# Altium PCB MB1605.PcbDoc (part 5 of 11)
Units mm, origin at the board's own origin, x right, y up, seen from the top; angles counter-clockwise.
Board outline 100 x 79.6 mm, 6 copper layers (Top Layer, Signal Layer 1, Signal Layer 2, Signal Layer 3, Signal Layer 4, Bottom Layer), stack 1.549 mm thick; 644 components, 529 nets, 2853 pads, 1462 vias.
Unrouted connection lines stored in the file: 2.
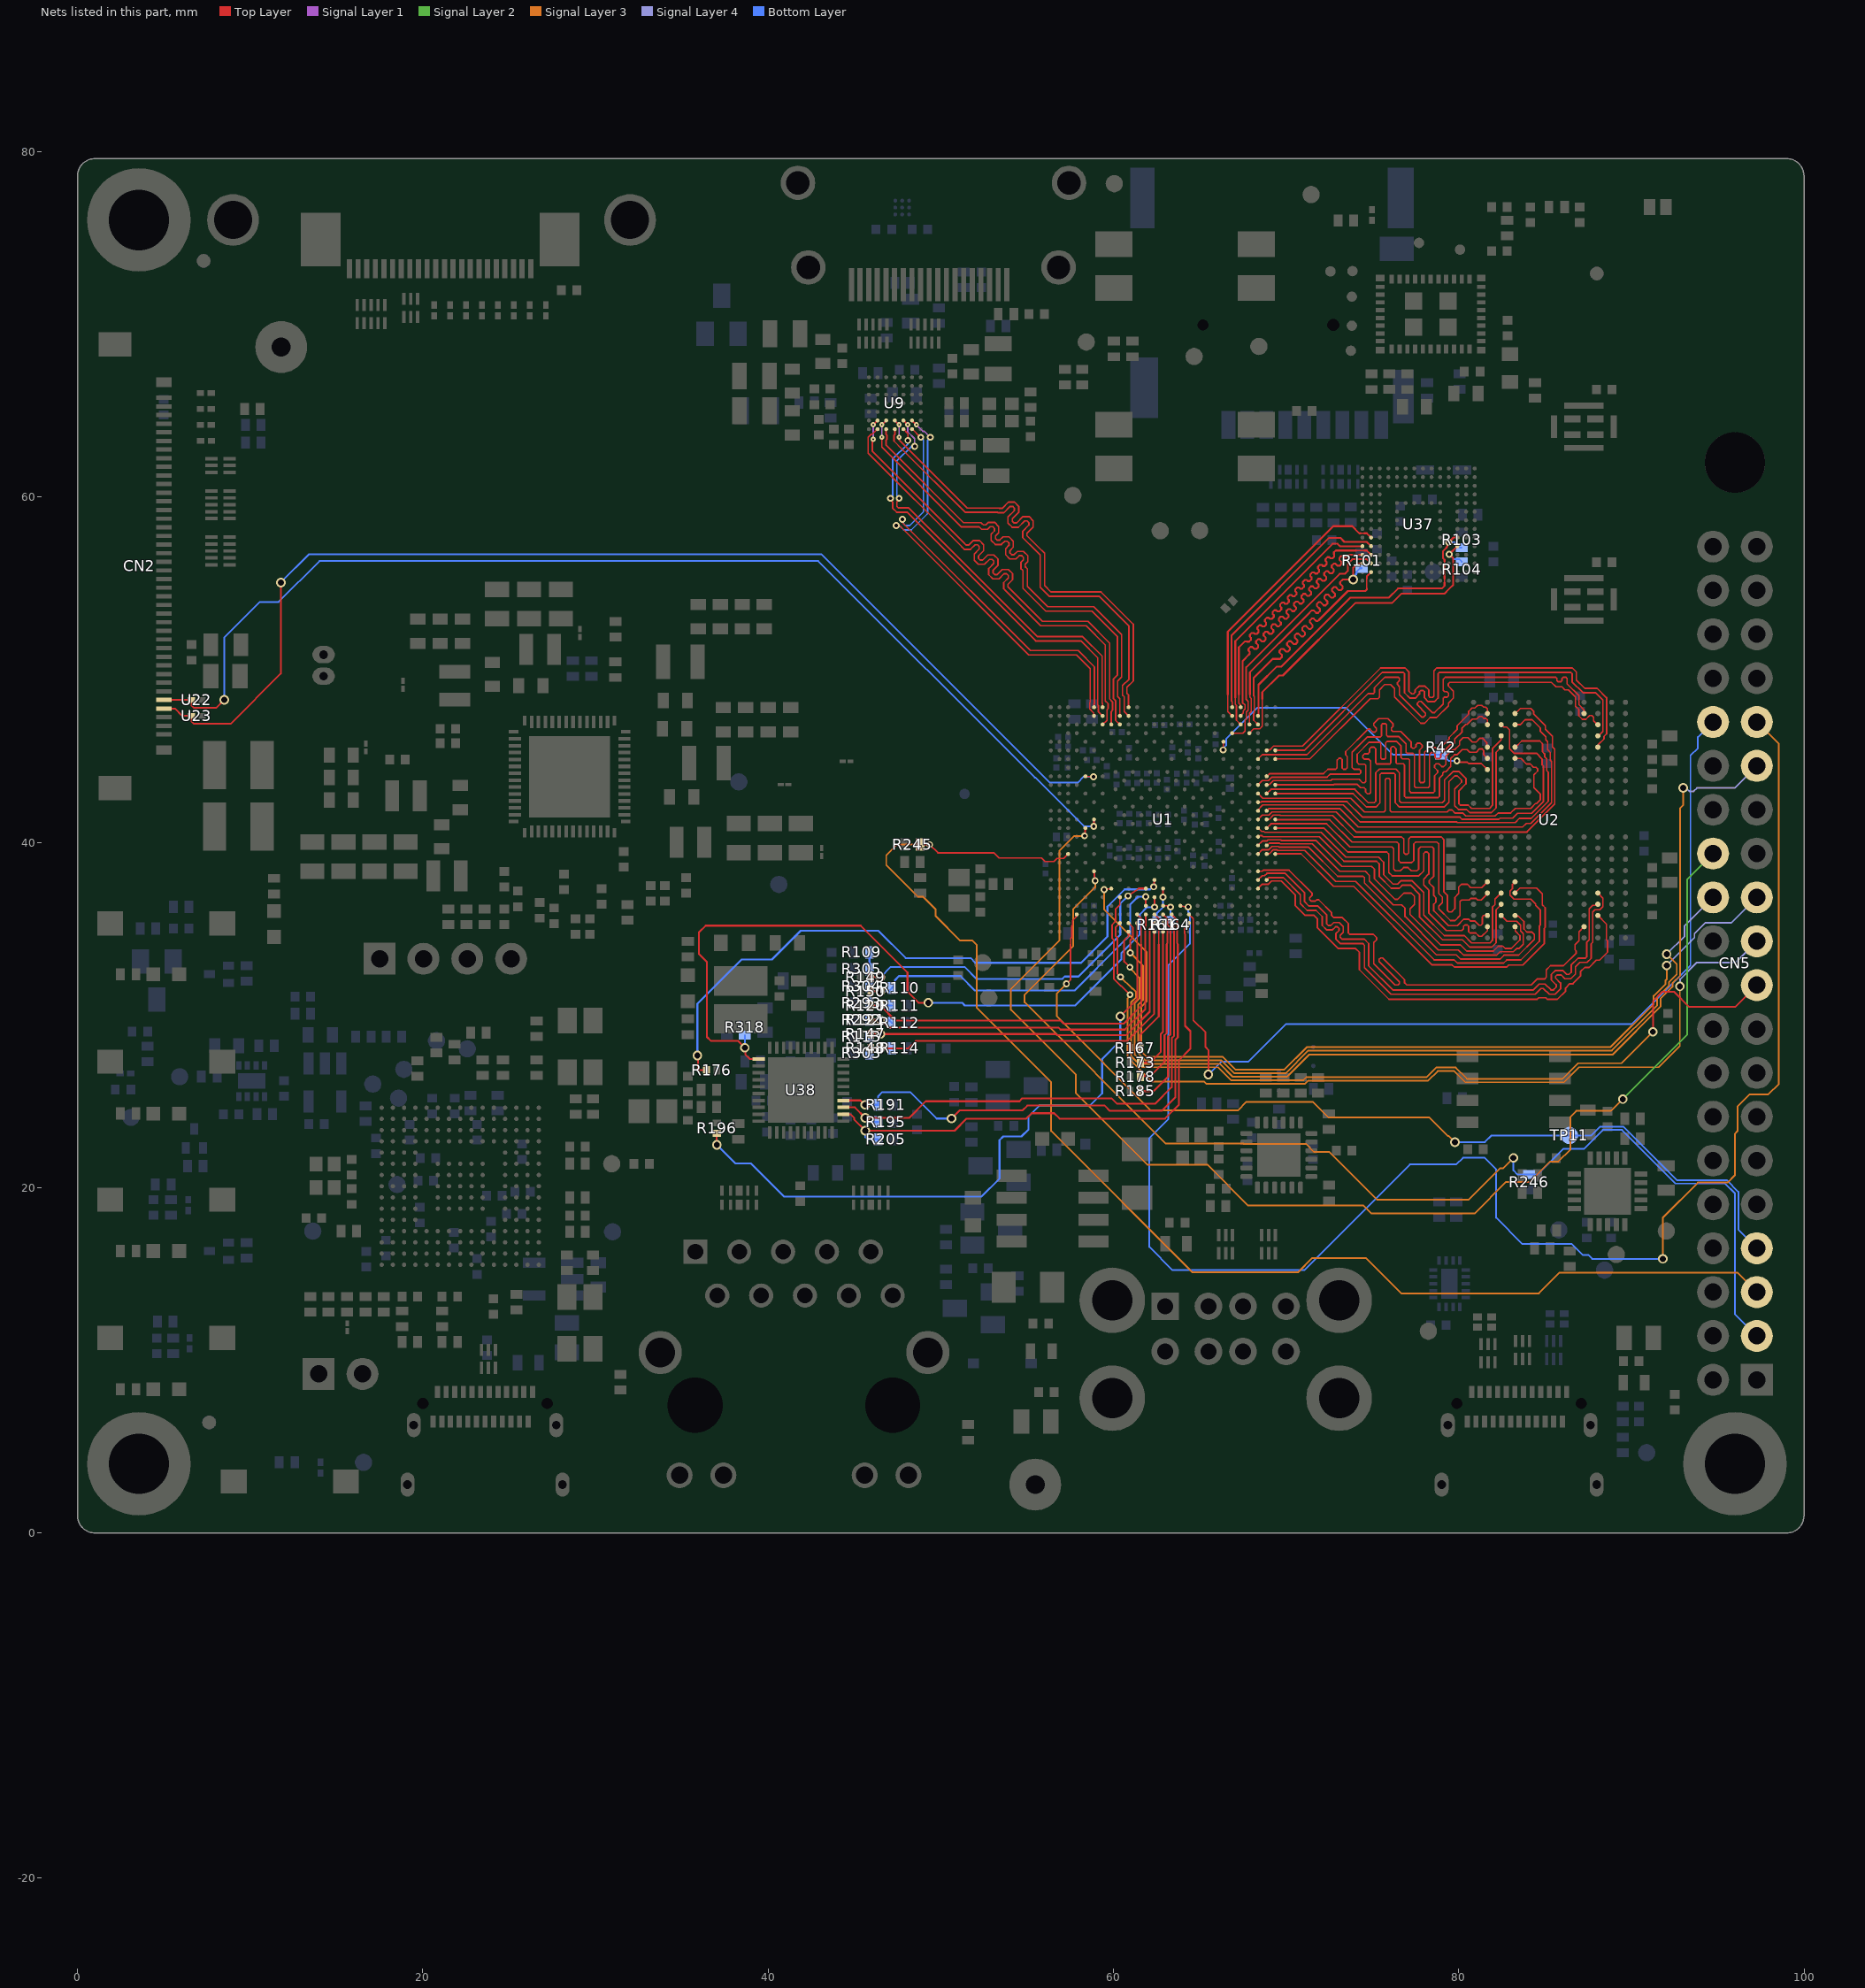
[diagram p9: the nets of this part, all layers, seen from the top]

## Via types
v1: diameter 0.55, hole 0.35, Top Layer to Bottom Layer, 823 vias
v2: diameter 0.4, hole 0.2, Top Layer to Bottom Layer, 235 vias
v3: diameter 0.4, hole 0.2, Top Layer to Bottom Layer, tented both sides, 216 vias
v4: diameter 0.5, hole 0.2, Top Layer to Bottom Layer, 159 vias
v5: diameter 0.25/0.3 (per signal layer), hole 0.1, Top Layer to Signal Layer 1, tented both sides, 29 vias

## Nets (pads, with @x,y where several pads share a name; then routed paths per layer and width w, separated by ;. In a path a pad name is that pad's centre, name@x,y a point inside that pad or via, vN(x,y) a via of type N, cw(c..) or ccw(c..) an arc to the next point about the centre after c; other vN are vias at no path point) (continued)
DDR_DQ7_A: U1.Y25 U2.B4 | length 29.9
  Top Layer w0.09: U1.Y25@68.375,38.325 68.62,38.325 68.682,38.387 70.174,38.387 71.498,37.064 71.498,36.927 71.365,36.794 71.365,36.68 71.444,36.601 71.698,36.601 71.771,36.674 71.888,36.674 72.636,35.926 72.636,35.768 72.76,35.644 73.257,35.644 73.606,35.296 73.606,34.757 73.682,34.681 75.04,34.681 75.246,34.476 75.246,34.362 75.076,34.192 75.076,32.969 76.305,31.74 76.487,31.74 76.565,31.818 76.565,31.925 75.391,33.098 75.391,33.218 75.481,33.307 75.593,33.307 76.865,32.035 76.865,31.863 76.988,31.74 84.199,31.74 84.54,32.082 84.963,32.082 85.073,32.191 85.073,32.614 85.316,32.858 86.072,32.858 86.807,33.593 86.807,33.701 86.731,33.777 86.731,34.064 86.964,34.297 86.964,34.819 U2.B4@87.26,35.115
DDR_DQ7_B: U1.G25 U2.AA4 | length 28.3
  Top Layer w0.09: U1.G25@68.377,44.829 68.623,45.075 71.214,45.075 74.754,48.614 75.062,48.614 75.12,48.672 75.12,48.958 75.722,49.56 76.504,49.56 76.569,49.494 76.569,49.369 76.455,49.254 76.455,49.134 76.569,49.02 76.569,48.547 77.854,47.262 77.97,47.262 78.08,47.372 78.08,47.483 77.609,47.954 77.609,48.064 77.706,48.161 77.814,48.161 78.456,47.518 78.6,47.518 79.099,48.016 79.099,48.341 79.169,48.412 79.329,48.412 79.403,48.485 79.403,48.642 79.316,48.729 79.17,48.729 79.099,48.8 79.099,49.443 79.216,49.56 85.622,49.56 ; 85.623,49.56 85.69,49.493 85.69,49.367 85.758,49.299 85.914,49.299 85.98,49.365 85.98,49.497 86.043,49.56 86.21,49.56 86.276,49.494 86.276,49.18 86.964,48.492 86.964,47.972 87.259,47.677 U2.AA4@87.259,47.444
DDR_DQ8_A: U1.R27 U2.B11 | length 20.4
  Top Layer w0.09: U1.R27@69.378,40.828 72.189,40.828 73.576,39.44 75.832,39.44 75.945,39.327 75.945,38.257 76.14,38.062 77.697,38.062 77.975,38.34 77.975,39.352 78.063,39.44 78.177,39.44 78.265,39.352 78.265,38.163 77.976,37.874 77.976,37.541 78.258,37.259 78.258,37.23 78.265,37.223 78.265,35.912 79.028,35.149 79.287,34.89 80.187,34.89 80.285,34.988 80.285,35.141 80.36,35.215 80.498,35.215 80.575,35.138 80.575,34.826 80.65,34.751 80.987,34.751 81.183,34.555 81.332,34.555 81.659,34.882 U2.B11@81.66,35.115
DDR_DQ8_B: U1.J26 U2.AA11 | length 23.9
  Top Layer w0.09: U1.J26@68.877,43.829 68.915,43.829 69.065,43.979 72.169,43.979 72.425,44.235 72.874,44.235 72.954,44.314 72.954,44.764 73.065,44.875 73.172,44.875 73.243,44.804 73.243,44.315 73.324,44.235 73.454,44.235 73.536,44.316 73.536,44.977 73.449,45.063 73.449,45.259 74.749,46.559 74.863,46.559 75.035,46.387 75.157,46.387 75.235,46.465 75.235,46.605 75.074,46.767 75.074,46.884 75.354,47.164 75.901,47.164 76.198,46.867 76.198,46.72 76.106,46.628 76.106,46.499 76.182,46.423 76.642,46.423 77.239,45.827 77.239,45.535 77.328,45.446 77.425,45.446 77.529,45.55 77.529,45.662 77.605,45.738 77.77,45.738 77.886,45.622 77.886,45.497 77.73,45.342 77.73,43.53 77.8,43.46 77.952,43.46 78.02,43.528 78.02,45.22 78.29,45.49 78.658,45.49 78.748,45.399 78.851,45.399 79.448,45.997 79.448,46.076 79.903,46.531 ; 79.904,46.531 79.904,46.746 80.575,47.417 80.575,47.583 80.771,47.779 80.931,47.779 81.091,47.939 81.34,47.939 81.449,47.83 81.563,47.83 81.659,47.734 U2.AA11@81.66,47.465
DDR_DQ9_A: U1.R26 U2.C11 | length 21.2
  Top Layer w0.09: U1.R26@68.875,40.825 69.125,41.075 72.352,41.075 73.697,39.73 76.134,39.73 76.235,39.629 76.235,38.453 76.336,38.352 76.622,38.352 76.809,38.539 77.063,38.539 77.25,38.352 77.577,38.352 77.685,38.46 77.685,39.625 77.79,39.73 78.453,39.73 78.555,39.628 78.555,38.043 78.292,37.78 78.292,37.635 78.555,37.372 78.555,36.912 78.676,36.791 78.676,36.538 78.555,36.417 78.555,36.032 79.407,35.18 79.914,35.18 ; 79.915,35.18 80.279,35.545 80.578,35.545 80.674,35.449 80.929,35.449 81.182,35.196 81.29,35.196 81.367,35.274 81.367,35.691 81.436,35.759 81.654,35.759 U2.C11@81.66,35.765
DDR_DQ9_B: U1.K25 U2.Y11 | length 23.9
  Top Layer w0.09: U1.K25@68.375,43.325 68.625,43.575 68.984,43.575 69.183,43.774 72.374,43.774 72.545,43.945 74.245,43.945 74.323,44.023 74.323,44.15 74.236,44.237 73.921,44.237 73.826,44.333 73.826,45.226 74.697,46.097 75.451,46.097 75.525,46.172 75.525,46.802 75.598,46.874 75.74,46.874 75.816,46.799 75.816,46.203 75.886,46.133 76.522,46.133 76.949,45.706 76.949,45.225 77.018,45.156 77.361,45.156 77.44,45.077 77.44,43.24 77.51,43.17 78.237,43.17 78.31,43.243 78.31,45.1 78.41,45.2 78.537,45.2 78.629,45.108 78.629,44.919 78.706,44.842 78.874,44.842 78.954,44.923 78.954,45.093 79.515,45.654 79.655,45.654 ; 79.656,45.654 79.765,45.763 79.765,45.982 79.769,45.982 80.194,46.407 80.194,46.626 80.403,46.835 80.477,46.835 80.783,47.142 81.038,47.142 81.196,47.3 81.327,47.3 81.447,47.18 81.577,47.18 81.659,47.097 U2.Y11@81.66,46.815
DDR_DQ10_A: U1.P27 U2.E11 | length 20.4
  Top Layer w0.09: U1.P27@69.377,41.329 69.401,41.305 72.532,41.305 73.817,40.02 76.417,40.02 76.525,39.912 76.525,38.936 76.632,38.829 77.276,38.829 77.395,38.948 77.395,39.902 77.513,40.02 78.731,40.02 78.845,39.906 78.845,37.032 79.049,36.828 79.049,36.501 78.845,36.297 78.845,36.152 79.527,35.47 79.795,35.47 80.08,35.755 80.08,36.576 80.171,36.667 80.608,36.667 80.69,36.749 81.006,36.749 81.1,36.655 81.304,36.655 81.66,37.01 U2.E11@81.66,37.065
DDR_DQ10_B: U1.K26 U2.V11 | length 23.8
  Top Layer w0.09: U1.K26@68.877,43.329 68.898,43.35 69.03,43.35 69.257,43.578 72.588,43.578 72.665,43.655 74.226,43.655 74.426,43.456 74.544,43.456 74.613,43.525 74.613,44.465 74.55,44.527 74.217,44.527 74.116,44.629 74.116,45.105 74.809,45.799 75.413,45.799 75.484,45.728 75.484,44.878 75.536,44.825 75.722,44.825 75.775,44.878 75.775,45.768 75.85,45.843 76.402,45.843 76.659,45.586 76.659,44.906 76.729,44.836 77.082,44.836 77.15,44.768 77.15,42.954 77.224,42.88 78.527,42.88 78.6,42.953 78.6,43.859 78.782,44.041 78.782,44.151 78.6,44.333 78.6,44.461 78.691,44.552 78.848,44.552 79.015,44.385 79.126,44.385 79.253,44.512 79.253,44.982 79.635,45.364 79.776,45.364 80.055,45.643 80.055,45.862 80.257,46.064 80.543,46.064 80.798,45.809 81.011,45.809 81.231,46.029 81.379,46.029 81.62,45.788 81.62,45.554 U2.V11@81.66,45.515
DDR_DQ11_A: U1.P26 U2.F11 | length 20.8
  Top Layer w0.09: U1.P26@68.877,41.329 68.887,41.339 69.035,41.339 69.271,41.575 69.638,41.575 69.658,41.555 72.692,41.555 73.937,40.31 76.699,40.31 76.815,40.194 76.815,39.398 76.897,39.316 77.031,39.316 77.105,39.39 77.105,40.203 77.212,40.31 79.002,40.31 79.135,40.177 79.135,37.152 79.342,36.945 79.342,36.066 79.439,35.968 79.583,35.968 79.779,36.165 79.779,36.816 80.002,37.04 80.002,37.417 80.155,37.569 80.502,37.569 80.697,37.374 81.331,37.374 U2.F11@81.666,37.709
DDR_DQ11_B: U1.K27 U2.U11 | length 23.1
  Top Layer w0.09: U1.K27@69.377,43.329 69.388,43.34 72.76,43.34 72.785,43.365 74.106,43.365 74.305,43.166 74.514,43.166 74.604,43.076 74.604,42.916 74.709,42.81 74.817,42.81 74.903,42.896 74.903,44.715 74.801,44.817 74.539,44.817 74.441,44.915 74.441,45.021 74.554,45.134 74.755,45.134 74.835,45.214 74.835,45.415 74.929,45.509 75.106,45.509 75.194,45.421 75.194,44.6 75.259,44.535 75.994,44.535 76.065,44.606 76.065,45.473 76.145,45.553 76.244,45.553 76.369,45.428 76.369,44.616 76.438,44.546 76.788,44.546 76.86,44.474 76.86,42.666 76.937,42.59 78.805,42.59 78.89,42.675 78.89,43.739 79.072,43.921 79.072,44.007 79.16,44.095 79.246,44.095 79.543,44.392 79.543,44.861 79.756,45.074 ; 79.757,45.074 79.896,45.074 80.196,45.374 80.482,45.374 80.636,45.22 81.018,45.22 81.212,45.414 81.35,45.414 81.44,45.324 81.44,45.085 U2.U11@81.66,44.865
DDR_DQ12_A: U1.V26 U2.F9 | length 24
  Top Layer w0.09: U1.V26@68.875,39.325 68.889,39.339 69.035,39.339 69.271,39.575 69.479,39.575 69.525,39.529 71.083,39.529 72.872,37.74 74.033,37.74 78.583,33.19 78.607,33.19 79.737,33.19 79.918,33.01 82.602,33.01 82.782,33.19 83.598,33.19 84.671,34.263 84.671,35.154 84.72,35.203 84.72,36.094 84.451,36.363 84.451,36.43 84.168,36.713 83.209,36.713 82.975,36.947 82.975,37.183 83.112,37.32 83.112,37.567 U2.F9@83.26,37.715
DDR_DQ12_B: U1.L25 U2.U9 | length 24.7
  Top Layer w0.09: U1.L25@68.377,42.829 68.647,42.559 73.739,42.559 74.537,41.76 75.661,41.76 75.74,41.839 75.74,43.628 75.817,43.705 75.956,43.705 76.03,43.631 76.03,41.834 76.105,41.76 79.329,41.76 79.441,41.872 79.607,41.872 79.791,41.689 ; 79.792,41.689 80.248,41.689 80.408,41.529 82.109,41.529 82.275,41.695 83.003,41.695 83.277,41.969 84.169,41.969 84.445,42.244 84.517,42.244 84.719,42.446 84.719,42.814 84.355,43.178 84.355,43.916 84.569,44.13 84.569,44.254 84.476,44.347 84.354,44.347 84.352,44.349 84.336,44.349 84.145,44.54 83.927,44.54 83.602,44.865 U2.U9@83.26,44.865
DDR_DQ13_A: U1.V27 U2.E9 | length 23.7
  Top Layer w0.09: U1.V27@69.377,39.329 69.387,39.339 70.863,39.339 72.752,37.45 73.913,37.45 78.462,32.9 78.465,32.9 79.616,32.9 79.737,32.78 ; 79.738,32.78 82.782,32.78 82.902,32.9 83.718,32.9 84.961,34.143 84.961,35.027 85.01,35.075 85.01,36.214 84.839,36.385 84.839,37.024 84.513,37.35 83.545,37.35 U2.E9@83.26,37.065
DDR_DQ13_B: U1.N25 U2.V9 | length 23.2
  Top Layer w0.09: U1.N25@68.377,41.829 68.377,41.891 68.653,42.167 73.311,42.167 74.297,41.18 79.884,41.18 ; 79.886,41.18 79.921,41.144 83.272,41.144 83.517,41.389 84.204,41.389 85.184,42.369 85.184,44.071 85.1,44.155 85.1,44.832 84.977,44.955 84.977,45.126 84.854,45.249 84.854,45.713 84.698,45.869 83.648,45.869 83.273,45.494 U2.V9@83.259,45.494
DDR_DQ14_A: U1.V25 U2.C9 | length 21.7
  Top Layer w0.09: U1.V25@68.377,39.329 68.623,39.575 69.003,39.575 69.193,39.765 69.557,39.765 69.603,39.719 71.303,39.719 72.992,38.03 74.466,38.03 74.535,37.961 74.535,37.648 78.703,33.48 79.858,33.48 80.098,33.24 82.4,33.24 82.63,33.47 83.468,33.47 84.381,34.383 84.381,34.666 84.25,34.797 83.958,34.797 83.775,34.98 83.775,35.413 83.463,35.725 83.3,35.725 U2.C9@83.26,35.765
DDR_DQ14_B: U1.N26 U2.Y9 | length 24
  Top Layer w0.09: U1.N26@68.875,41.825 69.008,41.958 73.109,41.958 74.177,40.89 83.701,40.89 83.91,41.099 84.183,41.099 85.374,42.29 85.374,44.689 85.307,44.756 85.307,45.206 85.144,45.369 85.144,45.833 85.044,45.933 85.044,46.117 84.729,46.432 84.729,46.632 84.725,46.632 84.257,47.1 83.84,47.1 83.554,46.814 U2.Y9@83.26,46.815
DDR_DQ15_A: U1.U25 U2.B9 | length 20.8
  Top Layer w0.09: U1.U25@68.377,39.829 68.625,40.077 68.894,40.077 68.956,40.14 69.692,40.14 69.727,40.104 71.739,40.104 73.233,38.61 74.955,38.61 75.115,38.45 75.115,37.888 76.306,36.697 76.458,36.697 76.816,37.055 77.259,37.055 77.435,36.879 77.435,36.413 77.178,36.156 77.178,35.825 78.943,34.06 80.098,34.06 80.458,33.7 82.011,33.7 82.293,33.982 82.56,33.982 82.687,33.855 83.053,33.855 83.545,34.347 83.545,34.593 83.28,34.858 83.28,35.073 U2.B9@83.259,35.094
DDR_DQ15_B: U1.P25 U2.AA9 | length 25.7
  Top Layer w0.09: U1.P25@68.377,41.329 68.623,41.575 69.003,41.575 69.193,41.765 72.892,41.765 74.057,40.6 83.953,40.6 85.564,42.211 85.564,45.392 85.434,45.522 85.434,46.138 85.019,46.553 85.019,46.752 84.345,47.426 84.345,47.583 84.178,47.75 83.572,47.75 U2.AA9@83.266,47.444
DDR_DQMI0_A: U1.AB25 U2.C3 | length 28.3
  Top Layer w0.09: U1.AB25@68.375,37.325 68.375,37.336 68.614,37.575 68.979,37.575 69.169,37.765 69.722,37.765 70.535,36.952 70.535,36.336 71.1,35.771 71.617,35.771 71.806,35.582 71.806,35.066 72.238,34.633 73.02,33.851 74.022,33.851 74.246,33.627 74.246,32.625 75.961,30.91 84.543,30.91 84.628,30.995 85.037,30.995 85.122,30.91 85.714,30.91 86.19,31.386 86.19,31.567 86.434,31.811 86.615,31.811 87.053,32.249 87.053,32.512 87.295,32.754 87.558,32.754 87.975,33.171 88.159,33.171 88.619,33.632 88.619,34.303 88.559,34.363 88.559,35.266 U2.C3@88.06,35.765
DDR_DQMI0_B: U1.G27 U2.Y3 | length 25.8
  Top Layer w0.09: U1.G27@69.377,44.829 71.378,44.829 74.874,48.324 75.323,48.324 75.41,48.412 75.41,48.838 75.708,49.136 76.043,49.136 76.279,48.9 76.279,48.426 77.807,46.898 78.017,46.898 78.346,47.228 78.721,47.228 79.403,47.911 79.403,48.068 79.693,48.358 ; 79.694,48.358 79.694,48.761 79.398,49.057 79.398,49.19 79.478,49.27 85.368,49.27 ; 85.369,49.27 85.63,49.009 85.981,49.009 86.156,48.834 86.353,48.834 86.764,48.423 86.764,47.889 86.952,47.701 86.952,47.333 87.16,47.126 87.365,47.126 87.587,47.347 87.719,47.347 87.815,47.251 87.815,47.033 88.034,46.815 U2.Y3@88.06,46.815
DDR_DQMI1_A: U1.U26 U2.C10 | length 20.8
  Top Layer w0.09: U1.U26@68.875,39.825 68.91,39.825 69.038,39.953 69.624,39.953 69.663,39.914 71.519,39.914 73.113,38.32 74.586,38.32 74.825,38.081 74.825,37.768 76.209,36.384 76.689,36.384 76.888,36.185 76.888,35.705 78.823,33.77 79.978,33.77 80.278,33.47 82.204,33.47 82.394,33.66 83.161,33.66 83.351,33.85 83.492,33.85 83.735,34.093 83.735,34.722 83.584,34.873 83.584,35.194 83.347,35.431 82.794,35.431 U2.C10@82.46,35.765
DDR_DQMI1_B: U1.M25 U2.Y10 | length 23.7
  Top Layer w0.09: U1.M25@68.375,42.325 68.378,42.328 68.545,42.328 68.574,42.357 73.531,42.357 74.417,41.47 80.05,41.47 80.181,41.339 82.329,41.339 82.395,41.405 83.123,41.405 83.397,41.679 84.221,41.679 84.909,42.367 84.909,44.413 84.824,44.498 84.824,44.839 84.505,45.159 83.208,45.159 82.944,45.423 82.944,46.513 82.781,46.677 82.618,46.677 82.479,46.815 U2.Y10@82.459,46.815
DDR_DQS0_A_N: U1.AA26 U2.E3 | length 30.5
  Top Layer w0.09: U1.AA26@68.875,37.825 68.875,37.832 68.998,37.955 69.843,37.955 70.825,36.973 70.825,36.456 71.22,36.061 71.737,36.061 72.096,35.702 72.096,35.186 72.346,34.935 72.695,34.935 72.863,35.104 72.982,35.104 73.066,35.02 73.066,34.896 72.882,34.712 72.882,34.399 73.14,34.141 74.43,34.141 74.536,34.036 74.536,32.746 76.081,31.2 84.422,31.2 84.764,31.542 84.9,31.542 85.242,31.2 85.594,31.2 85.9,31.506 85.9,31.852 85.613,32.139 85.613,32.242 85.688,32.318 85.933,32.318 86.149,32.101 86.495,32.101 86.763,32.369 86.763,32.785 87.022,33.044 87.438,33.044 87.671,33.277 87.671,34.119 87.764,34.212 87.764,35.978 87.885,36.099 88.181,36.099 88.354,36.272 88.354,36.771 U2.E3@88.06,37.065
DDR_DQS0_A_P: U1.AA25 U2.D3 | length 29.9
  Top Layer w0.09: U1.AA25@68.375,37.825 68.62,38.07 68.76,38.07 68.894,38.205 69.947,38.205 71.075,37.077 71.075,36.56 71.324,36.311 71.841,36.311 72.346,35.806 72.346,35.289 72.449,35.185 72.591,35.185 72.76,35.354 73.086,35.354 73.316,35.124 73.316,34.792 73.132,34.608 73.132,34.503 73.243,34.391 74.534,34.391 74.786,34.139 74.786,32.849 76.185,31.45 84.319,31.45 84.66,31.792 85.004,31.792 85.345,31.45 85.49,31.45 85.65,31.609 85.65,31.748 85.363,32.035 85.363,32.346 85.584,32.568 86.037,32.568 86.253,32.351 86.392,32.351 86.513,32.473 86.513,32.888 86.919,33.294 87.334,33.294 87.421,33.381 87.421,34.223 87.554,34.356 87.554,36.145 87.758,36.349 87.937,36.349 88.003,36.415 U2.D3@88.06,36.415
DDR_DQS0_B_N: U1.F26 U2.V3 | length 29.3
  Top Layer w0.09: U1.F26@68.877,45.329 68.904,45.356 69.05,45.356 69.273,45.579 70.955,45.579 75.475,50.1 76.893,50.1 77.109,49.883 77.109,48.77 77.278,48.602 77.383,48.602 77.477,48.696 77.477,48.829 77.692,49.044 78.052,49.044 78.269,48.827 78.269,48.469 78.34,48.398 78.492,48.398 78.559,48.465 78.559,49.937 78.722,50.1 86.587,50.1 86.816,49.872 86.816,49.404 87.299,48.92 88.022,48.92 88.564,48.378 88.564,46.284 88.414,46.134 88.414,45.997 88.093,45.676 88.093,45.528 U2.V3@88.059,45.494
DDR_DQS0_B_P: U1.F27 U2.W3 | length 27.5
  Top Layer w0.09: U1.F27@69.377,45.329 71.058,45.329 75.579,49.85 76.789,49.85 ; 76.795,49.843 76.859,49.78 76.859,48.667 77.174,48.352 77.487,48.352 77.727,48.592 77.727,48.726 77.795,48.794 77.949,48.794 78.019,48.724 78.019,48.366 78.236,48.148 78.595,48.148 78.809,48.362 78.809,49.777 78.882,49.85 86.484,49.85 86.566,49.768 86.566,49.3 87.196,48.67 87.918,48.67 88.354,48.234 88.354,46.427 88.071,46.144 U2.W3@88.059,46.144
DDR_DQS1_A_N: U1.R25 U2.E10 | length 20.7
  Top Layer w0.09: U1.R25@68.375,40.825 68.392,40.825 68.584,40.633 68.713,40.633 68.771,40.575 72.031,40.575 73.456,39.15 75.351,39.15 75.655,38.846 75.655,38.127 76.195,37.587 76.454,37.587 76.638,37.772 77.306,37.772 77.975,37.103 77.975,35.792 79.167,34.6 80.32,34.6 ; 80.321,34.6 80.742,34.18 81.812,34.18 81.954,34.322 81.954,36.243 82.104,36.393 82.104,36.709 U2.E10@82.46,37.065
DDR_DQS1_A_P: U1.T25 U2.D10 | length 20.3
  Top Layer w0.09: U1.T25@68.375,40.325 68.413,40.325 68.471,40.383 68.61,40.383 68.668,40.325 71.928,40.325 73.353,38.9 75.247,38.9 75.405,38.742 75.405,38.024 76.091,37.337 76.557,37.337 76.742,37.522 77.202,37.522 77.725,36.999 77.725,35.689 79.063,34.35 80.217,34.35 ; 80.218,34.351 80.638,33.93 81.916,33.93 82.164,34.178 82.164,36.099 U2.D10@82.459,36.394
DDR_DQS1_B_N: U1.L27 U2.V10 | length 24.1
  Top Layer w0.09: U1.L27@69.377,42.825 73.816,42.825 ; 73.827,42.825 73.883,42.825 74.658,42.05 75.208,42.05 75.443,42.285 75.443,43.927 75.511,43.995 76.251,43.995 76.32,43.926 76.32,42.298 76.569,42.05 79.156,42.05 79.43,42.324 79.43,43.515 79.765,43.85 ; 79.766,43.85 79.912,43.85 80.167,43.596 80.167,43.491 79.764,43.088 79.764,42.127 79.984,41.907 80.447,41.907 80.633,41.72 81.89,41.72 82.164,41.994 82.164,45.219 U2.V10@82.46,45.515
DDR_DQS1_B_P: U1.L26 U2.W10 | length 25.1
  Top Layer w0.09: U1.L26@68.877,42.829 68.879,42.829 69.125,43.075 73.986,43.075 74.761,42.3 75.105,42.3 75.193,42.388 75.193,44.031 75.407,44.245 76.355,44.245 76.57,44.03 76.57,42.402 76.672,42.3 79.052,42.3 79.18,42.427 79.18,43.618 79.662,44.1 ; 79.663,44.1 80.016,44.1 80.417,43.699 80.417,43.387 80.014,42.984 80.014,42.23 80.088,42.157 80.55,42.157 80.737,41.97 81.786,41.97 81.954,42.138 81.954,45.427 82.464,45.937 82.464,46.161 U2.W10@82.46,46.165
DDR_RESETN: R42.2 U1.E21 U2.T11 | length 18.6
  Top Layer w0.09: v3(66.35,45.35) 66.362,45.363 66.362,45.812 U1.E21@66.375,45.825 ; v2@79.881,44.707 79.994,44.707 80.065,44.636 80.492,44.636 80.562,44.565 81.31,44.565 U2.T11@81.66,44.215
  Bottom Layer w0.09: v3(66.35,45.35) 66.35,45.434 66.53,45.614 66.53,45.984 68.346,47.8 73.473,47.8 76.198,45.074 79.065,45.074 79.414,44.724 v2(79.895,44.725)
DISP.BLCTRL: CN2.37 U1.J5 U23.1 | length 67.7
  Top Layer w0.09: U1.J5@58.375,43.825 58.388,43.813 58.862,43.813 v3@58.875,43.8
  Top Layer w0.1: CN2.37@5,47.75 5.639,47.75 6.064,47.325 U23.1@6.596,47.325 6.596,47.009 6.738,46.867 8.873,46.867 11.775,49.769 v1(11.775,55.05)
  Bottom Layer w0.1: v1(11.775,55.05) 13.418,56.693 43.07,56.693 55.621,44.142 55.625,44.142 55.635,44.142 56.314,43.463 57.927,43.463 58.264,43.8 v3(58.85,43.8)
DISP.LED_EN: CN2.36 U1.P6 U22.1 | length 66.6
  Top Layer w0.09: v3(58.858,40.933) 58.877,40.952 58.877,41.323 U1.P6@58.875,41.325
  Top Layer w0.1: CN2.36@5,48.25 U22.1@6.596,48.25 6.596,47.934 6.738,47.792 8.033,47.792 v1(8.496,48.255)
  Bottom Layer w0.1: v1(8.496,48.255) 8.496,51.846 10.57,53.92 11.645,53.92 14.018,56.293 42.904,56.293 55.445,43.752 55.468,43.752 58.287,40.933 v3(58.858,40.933)
DSI_CLK_N: U1.C8 U9.F2 | length 28.3
  Top Layer w0.09: v5(46.086,63.342) 46.041,63.297 46.041,62.648 51.386,57.303 51.47,57.219 51.616,57.219 51.882,57.485 52.235,57.485 52.479,57.241 52.479,56.888 52.186,56.596 52.186,56.45 52.284,56.353 52.43,56.353 52.722,56.645 53.075,56.645 53.319,56.401 53.319,56.048 53.026,55.756 53.026,55.61 53.124,55.513 53.27,55.513 53.562,55.805 53.915,55.805 54.159,55.561 54.159,55.208 53.893,54.942 53.893,54.796 53.939,54.75 54.023,54.666 55.891,52.798 58.519,52.798 59.781,51.536 59.781,48.304 59.945,48.14 59.945,47.649 59.875,47.579 59.875,47.07 U1.C8@59.875,46.825 ; v5(46.086,64.185) U9.F2@46.336,64.435
  Signal Layer 1 w0.09: v5(46.086,63.342) v5(46.086,64.185)
DSI_CLK_P: U1.C7 U9.G2 | length 28.1
  Top Layer w0.09: U9.G2@46.336,63.935 46.038,63.637 45.964,63.637 45.791,63.464 45.791,62.544 51.21,57.126 51.293,57.042 51.367,56.969 51.72,56.969 51.986,57.235 52.132,57.235 52.229,57.138 52.229,56.992 51.936,56.699 51.936,56.346 52.18,56.103 52.533,56.103 52.826,56.395 52.972,56.395 53.069,56.298 53.069,56.152 52.776,55.859 52.776,55.506 53.02,55.263 53.373,55.263 53.666,55.555 53.812,55.555 53.909,55.458 53.909,55.312 53.643,55.046 53.643,54.693 53.762,54.573 53.846,54.489 55.788,52.548 58.415,52.548 59.531,51.432 59.531,48.2 59.695,48.036 59.695,47.752 59.625,47.682 59.625,47.174 59.625,47.073 59.377,46.825 U1.C7@59.375,46.825
DSI_D0_N: U1.C9 U9.F3 | length 28.2
  Top Layer w0.09: v5(46.586,63.464) 46.586,62.892 51.208,58.27 52.183,58.27 52.229,58.27 52.29,58.209 52.363,58.136 52.716,58.136 52.864,58.284 53.01,58.284 53.107,58.186 53.107,58.04 52.917,57.851 52.917,57.498 53.161,57.254 53.514,57.254 53.704,57.444 53.85,57.444 53.947,57.346 53.947,57.2 53.757,57.011 53.757,56.658 54.001,56.414 54.354,56.414 54.544,56.604 54.69,56.604 54.787,56.506 54.787,56.36 54.639,56.213 54.639,55.86 54.729,55.77 54.764,55.735 54.764,55.638 54.764,54.715 56.082,53.397 58.764,53.397 60.225,51.936 60.225,49.675 59.995,49.445 59.995,48.575 59.995,48.344 60.068,48.271 60.125,48.214 60.125,47.429 60.125,47.075 U1.C9@60.375,46.825 ; v5(46.586,64.185) U9.F3@46.836,64.435
  Signal Layer 1 w0.09: v5(46.586,63.464) v5(46.586,64.185)
DSI_D0_P: U1.B9 U9.G3 | length 27
  Top Layer w0.09: U9.G3@46.836,63.935 46.836,63.631 46.881,63.586 46.881,63.342 46.836,63.297 46.836,62.996 51.312,58.52 52.332,58.52 52.383,58.47 52.466,58.386 52.612,58.386 52.76,58.534 53.113,58.534 53.357,58.29 53.357,57.937 53.167,57.747 53.167,57.601 53.264,57.504 53.41,57.504 53.6,57.694 53.953,57.694 54.197,57.45 54.197,57.097 54.007,56.907 54.007,56.761 54.104,56.664 54.25,56.664 54.44,56.854 54.793,56.854 55.037,56.61 55.037,56.257 54.889,56.109 54.889,55.963 54.906,55.947 54.989,55.863 55.014,55.838 55.014,54.818 56.185,53.647 58.868,53.647 60.475,52.04 60.475,49.571 60.245,49.341 60.245,48.575 60.245,48.448 60.375,48.318 U1.B9@60.375,47.325
DSI_D1_N: U1.A10 U9.F4 | length 28
  Top Layer w0.09: U9.F4@47.336,64.435 v5(47.586,64.185) ; v5@47.598,63.452 v5(47.586,63.464) 47.586,63.301 51.523,59.364 53.26,59.364 53.391,59.364 53.409,59.346 53.555,59.346 53.916,59.707 54.269,59.707 54.513,59.463 54.513,59.11 54.144,58.741 54.144,58.595 54.242,58.498 54.387,58.498 54.756,58.867 55.109,58.867 55.353,58.623 55.353,58.27 54.992,57.909 54.992,57.763 55.659,57.097 56.014,56.741 56.014,54.873 56.382,54.505 59.278,54.505 61.15,52.633 61.15,49.346 60.78,48.976 60.78,48.632 60.875,48.537 U1.A10@60.875,47.825
  Signal Layer 1 w0.09: v5(47.586,63.464) v5(47.586,64.185)
DSI_D1_P: U1.B10 U9.G4 | length 28
  Top Layer w0.09: U9.G4@47.336,63.935 47.336,63.631 47.291,63.586 47.291,63.242 47.754,62.78 51.419,59.114 53.208,59.114 53.288,59.114 53.306,59.096 53.659,59.096 54.02,59.457 54.166,59.457 54.263,59.359 54.263,59.213 53.894,58.845 53.894,58.492 54.138,58.248 54.491,58.248 54.86,58.617 55.006,58.617 55.103,58.519 55.103,58.373 54.742,58.013 54.742,57.66 55.482,56.92 55.764,56.638 55.764,54.77 56.279,54.255 59.174,54.255 60.9,52.529 60.9,49.45 60.53,49.08 60.53,48.575 60.53,48.529 60.625,48.434 60.625,47.575 U1.B10@60.875,47.325
DSI_D2_N: U1.A7 U9.F5 | length 24.3
  Top Layer w0.09: v2(47.586,59.926) 47.586,59.844 47.461,59.719 47.461,59.458 47.547,59.372 48.141,59.372 55.597,51.916 58.216,51.916 59.341,50.792 59.341,48.066 59.375,48.032 U1.A7@59.375,47.825 ; U9.F5@47.836,64.435 v5(48.086,64.185)
  Signal Layer 1 w0.09: v5(48.086,64.185) 48.086,63.78 48.487,63.379 v2(48.487,62.933)
  Bottom Layer w0.09: v2(47.586,59.926) 47.461,60.051 47.461,62.099 48.294,62.933 v2(48.487,62.933)
DSI_D2_P: U1.B7 U9.G5 | length 24.1
  Top Layer w0.09: v2(47.086,59.926) 47.086,59.844 47.211,59.719 47.211,59.354 47.443,59.122 48.037,59.122 55.493,51.666 58.113,51.666 59.091,50.688 59.091,47.963 59.125,47.929 59.125,47.575 U1.B7@59.375,47.325 ; U9.G5@47.836,63.935 48.095,63.676 v2(48.095,63.28)
  Bottom Layer w0.09: v2(47.086,59.926) 47.211,60.051 47.211,62.203 48.095,63.087 v2(48.095,63.28)
DSI_D3_N: U1.B6 U9.F6 | length 25.8
  Top Layer w0.09: v2(47.425,58.348) 47.601,58.348 55.092,50.857 57.854,50.857 58.65,50.061 58.65,48.127 58.625,48.102 58.625,47.721 58.86,47.486 58.86,47.34 U1.B6@58.875,47.325 ; U9.F6@48.336,64.435 v5(48.586,64.185)
  Signal Layer 1 w0.09: v5(48.586,64.185) 48.962,63.81 49.039,63.81 v2(49.389,63.46)
  Bottom Layer w0.09: v2(47.425,58.348) 47.483,58.29 47.66,58.29 47.854,58.095 48.291,58.095 49.239,59.043 49.239,63.311 v2(49.389,63.46)
DSI_D3_P: U1.A6 U9.G6 | length 24
  Top Layer w0.09: v2(47.778,58.702) 47.778,58.525 48.241,58.062 55.196,51.107 57.958,51.107 58.9,50.165 58.9,48.024 58.875,47.999 U1.A6@58.875,47.825 ; U9.G6@48.336,63.935 48.352,63.935 48.824,63.462 v2(48.84,63.462)
  Bottom Layer w0.09: v2(47.778,58.702) 47.837,58.643 47.837,58.466 47.958,58.345 48.188,58.345 48.989,59.147 48.989,63.313 v2(48.84,63.462)
eMMC.SDMMC2_CK: R103.1 U1.B25 U37.M6 | length 19.1
  Top Layer w0.09: U1.B25@68.375,47.325 68.402,47.352 68.402,48.575 ; 79.175,55.037 79.175,55.273 ; 79.175,55.537 79.175,55.773 ; 79.175,56.037 79.175,56.273
  Top Layer w0.11: 68.402,48.575 68.402,49.127 69.459,50.184 69.734,50.184 73.725,54.175 75.95,54.175 76.481,54.706 79.022,54.706 79.175,54.858 79.175,55.037 ; 79.175,55.273 79.175,55.405 ; 79.175,55.407 79.175,55.537 ; 79.175,55.773 79.175,55.905 ; 79.175,55.907 79.175,56.037 ; 79.175,56.273 79.175,56.372 79.095,56.452 79.095,56.87 79.281,57.056 v2(79.425,57.375) 79.705,57.655 U37.M6@79.925,57.655
  Bottom Layer w0.11: v2(79.425,57.375) 79.762,57.375 80.076,57.061 R103.1@80.171,57.061
eMMC.SDMMC2_CMD: R104.1 U1.D24 U37.M5 | length 19.9
  Top Layer w0.09: U1.D24@67.875,46.325 68.125,46.575 68.479,46.575 68.625,46.721 ; 68.625,46.725 68.625,48.305 ; 79.675,55.037 79.675,55.273 ; 79.675,55.537 79.675,55.773 ; 79.675,56.037 79.675,56.273
  Top Layer w0.11: 68.625,48.305 68.625,48.699 69.588,49.662 69.816,49.662 74.029,53.875 76.15,53.875 76.674,54.399 79.162,54.399 79.469,54.705 79.675,54.911 79.675,55.037 ; 79.675,55.273 79.675,55.405 ; 79.675,55.407 79.675,55.537 ; 79.675,55.773 79.675,55.905 ; 79.675,55.907 79.675,56.037 ; 79.675,56.273 79.675,56.46 v2(79.45,56.685) U37.M5@79.92,57.155
  Bottom Layer w0.11: v2(79.45,56.685) 79.724,56.411 80.019,56.411 R104.1@80.175,56.255
eMMC.SDMMC2_D0: R101.1 U1.C24 U37.A3 | length 16
  Top Layer w0.09: U1.C24@67.875,46.825 67.88,46.83 67.88,47.467 67.985,47.572 67.985,48.335 67.902,48.418 67.902,48.575
  Top Layer w0.11: 67.902,48.575 67.902,49.85 71.229,53.177 71.487,53.435 71.597,53.435 71.743,53.289 71.852,53.289 71.962,53.399 71.962,53.508 71.778,53.692 71.778,53.801 71.888,53.911 71.998,53.911 72.181,53.727 72.291,53.727 72.4,53.837 72.4,53.947 72.217,54.13 72.217,54.24 72.326,54.349 72.436,54.349 72.62,54.166 72.729,54.166 72.839,54.275 72.839,54.385 72.655,54.569 72.655,54.678 72.765,54.788 72.874,54.788 73.058,54.604 73.168,54.604 73.277,54.714 73.277,54.823 73.131,54.969 73.131,55.079 73.279,55.227 v1(73.884,55.227) 73.884,55.909 74.13,56.155 U37.A3@74.425,56.155
  Bottom Layer w0.11: v1(73.884,55.227) 73.884,55.34 74.056,55.512 74.056,55.556 74.08,55.58 74.08,55.675 74.28,55.875 R101.1@74.375,55.875
eMMC.SDMMC2_D1: U1.B23 U37.A4 | length 18.8
  Top Layer w0.09: U1.B23@67.375,47.325 67.375,47.357 67.52,47.502 67.52,47.616 67.625,47.721 67.625,47.952 67.479,48.098 67.479,48.575
  Top Layer w0.11: 67.479,48.575 67.479,50.504 67.856,50.881 67.895,50.92 67.895,51.03 67.824,51.101 67.824,51.21 67.934,51.32 68.044,51.32 68.165,51.199 68.274,51.199 68.384,51.308 68.384,51.418 68.263,51.539 68.263,51.649 68.372,51.758 68.482,51.758 68.603,51.637 68.713,51.637 68.822,51.747 68.822,51.856 68.701,51.977 68.701,52.087 68.811,52.197 68.92,52.197 69.042,52.075 69.151,52.075 69.261,52.185 69.261,52.295 69.14,52.416 69.14,52.525 69.249,52.635 69.359,52.635 69.48,52.514 69.59,52.514 69.699,52.623 69.699,52.733 69.578,52.854 69.578,52.964 69.688,53.073 69.797,53.073 69.918,52.952 70.028,52.952 70.138,53.062 70.138,53.171 70.016,53.293 70.016,53.402 70.126,53.512 70.236,53.512 70.357,53.391 70.466,53.391 70.576,53.5 70.576,53.61 70.455,53.731 70.455,53.841 70.564,53.95 70.674,53.95 70.795,53.829 70.905,53.829 71.014,53.939 71.014,54.048 70.893,54.169 70.893,54.279 71.003,54.389 71.112,54.389 71.234,54.267 71.343,54.267 71.453,54.377 71.453,54.487 71.332,54.608 71.332,54.718 71.441,54.827 71.551,54.827 71.672,54.706 71.782,54.706 71.891,54.815 71.891,54.925 71.77,55.046 71.77,55.156 71.88,55.266 71.989,55.266 72.11,55.144 72.22,55.144 72.33,55.254 72.33,55.363 72.208,55.485 72.208,55.594 72.318,55.704 72.428,55.704 72.549,55.583 72.658,55.583 72.768,55.692 72.768,55.802 72.647,55.923 72.647,56.033 72.756,56.142 72.866,56.142 72.987,56.021 73.097,56.021 73.206,56.131 73.206,56.24 73.085,56.362 73.085,56.471 73.195,56.581 73.304,56.581 73.375,56.51 73.485,56.51 73.536,56.561 73.63,56.655 U37.A4@74.425,56.655
eMMC.SDMMC2_D2: U1.C23 U37.A5 | length 14.7
  Top Layer w0.09: 67.055,48.395 67.055,47.999 67.125,47.929 67.125,47.075 U1.C23@67.375,46.825
  Top Layer w0.11: 67.054,48.395 67.057,48.398 67.057,51.657 72.691,57.291 72.984,57.291 73.12,57.155 74.056,57.155 U37.A5@74.425,57.155
eMMC.SDMMC2_D3: U1.C25 U37.B2 | length 15.5
  Top Layer w0.09: 68.125,48.575 68.125,48.489 68.165,48.449 68.165,47.498 68.125,47.458 68.125,47.075 U1.C25@68.375,46.825 ; 74.675,54.705 74.675,55.273
  Top Layer w0.11: 68.125,48.575 68.125,49.525 69.225,50.625 69.647,50.625 69.723,50.702 69.762,50.741 69.762,50.85 69.621,50.991 69.621,51.101 69.731,51.211 69.84,51.211 70.004,51.046 70.114,51.046 70.224,51.156 70.224,51.266 70.059,51.43 70.059,51.539 70.169,51.649 70.279,51.649 70.443,51.485 70.552,51.485 70.662,51.594 70.662,51.704 70.498,51.868 70.498,51.978 70.607,52.087 70.717,52.087 70.881,51.923 70.991,51.923 71.1,52.033 71.1,52.142 70.936,52.307 70.936,52.416 71.046,52.526 71.155,52.526 71.32,52.362 71.429,52.362 71.539,52.471 71.539,52.581 71.375,52.745 71.375,52.855 71.484,52.964 71.594,52.964 71.735,52.823 71.845,52.823 71.887,52.865 73.582,54.56 74.596,54.56 74.675,54.639 74.675,54.705 ; 74.675,55.273 74.675,55.405 U37.B2@74.925,55.655
eMMC.SDMMC2_D4: U1.D22 U37.B3 | length 14.8
  Top Layer w0.09: U1.D22@66.875,46.325 67.5,46.325 67.625,46.45 67.625,47.075 67.7,47.15 67.7,47.541 67.805,47.647 67.805,48.17 67.7,48.275 ; 74.056,56.405 74.543,56.405
  Top Layer w0.11: 67.7,48.275 67.692,48.283 67.692,50.142 73.1,55.55 73.4,55.55 73.575,55.725 73.575,56.125 73.855,56.405 74.056,56.405 ; 74.543,56.405 74.675,56.405 U37.B3@74.925,56.155
eMMC.SDMMC2_D5: U1.A23 U37.B4 | length 17.3
  Top Layer w0.09: 67.267,48.575 67.267,48.055 67.349,47.973 67.349,47.851 U1.A23@67.375,47.825 ; 74.056,56.905 74.543,56.905
  Top Layer w0.11: 67.267,48.575 67.267,51.292 67.362,51.387 67.621,51.646 67.73,51.646 67.75,51.625 67.86,51.625 67.97,51.735 67.97,51.845 67.901,51.913 67.901,52.022 68.011,52.132 68.121,52.132 68.189,52.064 68.298,52.064 68.408,52.173 68.408,52.283 68.34,52.351 68.34,52.461 68.449,52.57 68.559,52.57 68.627,52.502 68.737,52.502 68.846,52.612 68.846,52.721 68.778,52.79 68.778,52.899 68.888,53.009 68.997,53.009 69.066,52.941 69.175,52.941 69.285,53.05 69.285,53.16 69.217,53.228 69.217,53.338 69.326,53.447 69.436,53.447 69.504,53.379 69.614,53.379 69.723,53.489 69.723,53.598 69.655,53.666 69.655,53.776 69.765,53.886 69.874,53.886 69.942,53.817 70.052,53.817 70.162,53.927 70.162,54.037 70.093,54.105 70.093,54.214 70.203,54.324 70.313,54.324 70.381,54.256 70.49,54.256 70.6,54.365 70.6,54.475 70.532,54.543 70.532,54.653 70.641,54.762 70.751,54.762 70.819,54.694 70.929,54.694 71.038,54.804 71.038,54.913 70.97,54.982 70.97,55.091 71.08,55.201 71.189,55.201 71.258,55.133 71.367,55.133 71.477,55.242 71.477,55.352 71.409,55.42 71.409,55.53 71.518,55.639 71.628,55.639 71.696,55.571 71.806,55.571 71.915,55.681 71.915,55.79 71.847,55.858 71.847,55.968 71.957,56.078 72.066,56.078 72.134,56.01 72.244,56.01 72.354,56.119 72.354,56.229 72.285,56.297 72.285,56.406 72.395,56.516 72.505,56.516 72.573,56.448 72.682,56.448 72.792,56.558 72.792,56.667 72.772,56.687 72.772,56.797 72.88,56.905 72.912,56.905 74.056,56.905 ; 74.543,56.905 74.675,56.905 U37.B4@74.925,56.655
eMMC.SDMMC2_D6: U1.A22 U37.B5 | length 14.8
  Top Layer w0.09: 66.847,48.356 66.847,48.176 66.875,48.148 U1.A22@66.875,47.825 ; 74.056,57.405 74.675,57.405
  Top Layer w0.096: 66.847,48.356 66.847,48.575
  Top Layer w0.11: 66.847,48.575 66.847,51.997 72.49,57.64 73.14,57.64 73.375,57.405 74.056,57.405 ; 74.675,57.405 U37.B5@74.925,57.155
eMMC.SDMMC2_D7: U1.B22 U37.B6 | length 16.1
  Top Layer w0.09: 66.625,48.575 66.625,47.575 U1.B22@66.875,47.325 ; 74.307,57.905 74.543,57.905
  Top Layer w0.11: 66.625,48.575 66.625,52.197 72.738,58.31 73.836,58.31 74.241,57.905 74.307,57.905 ; 74.543,57.905 74.675,57.905 U37.B6@74.925,57.655
ETH1.CLK: R196.1 U1.AF11 | length 39.2
  Top Layer w0.09: 61.375,34.075 U1.AF11@61.375,35.325
  Top Layer w0.11: v1(37.025,22.475) R196.1@37.025,23.15 ; v1(60.4,29.925) 61.375,30.9 61.375,34.075
  Bottom Layer w0.11: v1(37.025,22.475) 38.09,21.41 38.992,21.41 40.925,19.477 52.35,19.477 53.4,20.527 53.4,22.745 53.617,22.963 54.673,22.963 55.085,23.374 55.085,24.123 55.711,24.75 58.631,24.75 59.345,25.464 59.345,27.451 60.4,28.506 v1(60.4,29.925)
ETH1.CLK125: R176.1 U1.AA13 | length 36.5
  Top Layer w0.11: v1(35.905,27.657) 35.938,27.625 35.938,26.864 36.002,26.8 R176.1@36.425,26.8 ; v3(62.325,37.425) U1.AA13@62.375,37.825
  Bottom Layer w0.11: v1(35.905,27.657) 35.905,30.656 38.461,33.211 40.216,33.211 41.887,34.883 46.382,34.883 47.968,33.297 51.728,33.297 52,33.025 58.13,33.025 59.18,34.075 59.653,34.548 59.653,36.273 60.654,37.274 62.116,37.274 62.266,37.425 v3(62.325,37.425)
ETH1.GTX_CLK: R161.1 U1.AB14 | length 2
  Top Layer w0.11: v3(62.875,36.825) U1.AB14@62.875,37.325
  Bottom Layer w0.11: R161.1@62.506,35.525 62.506,35.879 62.875,36.248 v3(62.875,36.825)
ETH1.MDC: R195.1 U1.AF15 U38.13 | length 30.7
  Top Layer w0.09: U1.AF15@63.375,35.318 63.375,35.293 63.515,35.153 63.515,34.075
  Top Layer w0.11: U38.13@44.35,24.65 45.02,24.65 v1(45.625,24.045) 48.17,24.045 49.13,25.005 54.552,25.005 54.724,25.178 59.89,25.178 60.214,24.853 62.409,24.853 63.377,25.821 63.377,28.652 63.515,28.79 63.515,34.075
  Bottom Layer w0.11: v1(45.625,24.045) 45.87,23.8 R195.1@46.37,23.8
ETH1.MDINT: R318.1 U1.AC13 U38.31 | length 43.6
  Top Layer w0.11: U38.31@39.45,27.45 38.95,27.45 38.676,27.724 38.676,28.074 v1(38.65,28.1) 38.245,28.505 36.677,28.505 36.455,28.727 36.455,33.075 35.985,33.545 35.985,34.775 36.385,35.175 45.356,35.175 48.07,32.461 48.07,31.354 48.714,30.71 v1(49.28,30.71) ; v3(62.375,36.25) U1.AC13@62.375,36.825
  Bottom Layer w0.11: v1(38.65,28.1) R318.1@38.65,28.825 ; v1(49.28,30.71) 51.233,30.71 51.394,30.55 57.777,30.55 60.458,33.23 60.458,33.588 61.525,34.655 61.525,35.82 61.94,36.235 62.36,36.235 v3(62.375,36.25)
ETH1.MDIO: R191.1 U1.AE15 U38.14 | length 32.1
  Top Layer w0.09: U1.AE15@63.375,35.825 63.695,35.505 63.695,34.164 63.725,34.134 63.725,34.075
  Top Layer w0.11: U38.14@44.35,25.05 45.344,25.05 45.594,24.8 v1(45.625,24.8) ; v1(50.625,24) 51.1,24.475 54.742,24.475 55.017,24.75 59.493,24.75 59.787,24.455 62.803,24.455 63.587,25.24 63.587,28.565 63.725,28.703 63.725,34.075
  Bottom Layer w0.11: v1(45.625,24.8) R191.1@46.37,24.8 46.37,25.292 46.611,25.533 48.232,25.533 49.764,24 v1(50.625,24)
ETH1.NRST: R205.1 U1.AF17 U38.12 | length 33
  Top Layer w0.09: 64.154,34.075 64.154,34.693 64.125,34.721 64.125,35.075 U1.AF17@64.375,35.325
  Top Layer w0.1: U38.12@44.35,24.25 44.775,24.25 44.98,24.045 44.98,23.945 v1(45.625,23.3)
  Top Layer w0.11: v1(45.625,23.3) 50.8,23.3 51.495,23.995 54.956,23.995 55.272,24.311 56.565,24.311 56.881,23.995 62.986,23.995 63.797,24.806 63.797,27.389 64.457,28.048 64.457,29.066 64.154,29.369 64.154,34.075
  Bottom Layer w0.11: v1(45.625,23.3) 45.637,23.288 45.637,22.924 45.761,22.8 R205.1@46.37,22.8
ETH1.RX_CLK: R109.1 R149.1 R305.2 U1.AB12 | length 21.4
  Top Layer w0.11: R149.1@45.945,32.185 v1(46.501,32.185) ; v3(60.842,36.894) 61.475,37.325 U1.AB12@61.875,37.325
  Bottom Layer w0.11: R109.1@45.87,33.625 R305.2@45.87,32.651 45.87,32.579 46.07,32.379 46.217,32.379 v1@46.411,32.185 ; v1(46.501,32.185) 47.103,32.786 51.372,32.786 52.079,32.08 57.028,32.08 57.176,32.227 57.977,32.227 60.4,34.65 60.4,36.452 v3(60.842,36.894)
ETH1.RX_CTL: R110.1 R150.1 R304.2 U1.AD12 | length 21.4
  Top Layer w0.11: R150.1@45.945,31.365 v1(46.501,31.365) ; U1.AD12@61.875,36.325 v3(61.875,36.85)
  Bottom Layer w0.11: R304.2@45.87,31.67 46.175,31.365 v1(46.501,31.365) 46.97,31.365 47.339,31.735 47.339,32.014 47.575,32.25 51.144,32.25 51.969,31.425 57.752,31.425 60.402,34.075 60.975,34.648 60.975,36.4 61.425,36.85 v3(61.875,36.85)
ETH1.RXD0: R111.1 R120.1 R293.2 U1.AE11 | length 23.3
  Top Layer w0.09: U1.AE11@61.375,35.825 61.625,35.575 61.625,35.221 61.605,35.201 61.605,34.075
  Top Layer w0.11: R120.1@45.945,30.544 v1(46.501,30.545) ; v1(46.501,30.545) 47.371,29.675 56.933,29.675 57.113,29.495 60.595,29.495 61.605,30.505 61.605,34.075
  Bottom Layer w0.11: R293.2@45.87,30.688 46.014,30.545 v1(46.501,30.545) R111.1@47.17,30.545
ETH1.RXD1: R112.1 R121.1 R292.2 U1.AE12 | length 23.5
  Top Layer w0.11: R121.1@45.945,29.72 v1(46.501,29.72) ; v1(46.501,29.72) 46.946,29.275 56.813,29.275 56.938,29.15 60.654,29.15 61.85,30.346 61.85,34.075 61.85,35.15 61.875,35.175 ; 61.875,35.178 U1.AE12@61.875,35.793
  Bottom Layer w0.11: R292.2@45.87,29.72 v1(46.501,29.72) 46.98,29.72 R112.1@47.17,29.53
ETH1.RXD2: R113.2 R147.1 U1.AF13 | length 22.7
  Top Layer w0.09: 62.1,34.075 62.1,35.05 U1.AF13@62.375,35.325
  Top Layer w0.11: R147.1@45.945,28.898 v1(46.501,28.898) ; v1(46.501,28.898) 56.657,28.898 56.73,28.825 60.735,28.825 62.1,30.19 62.1,34.075
  Bottom Layer w0.11: R113.2@45.87,28.75 46.018,28.898 v1(46.501,28.898)
ETH1.RXD3: R114.1 R148.1 R303.2 U1.AG13 | length 23.4
  Top Layer w0.09: 62.362,34.075 62.362,34.812 U1.AG13@62.375,34.825
  Top Layer w0.11: R148.1@45.944,28.065 48.132,28.065 48.562,28.495 60.776,28.495 62.362,30.081 62.362,34.075
  Bottom Layer w0.11: R303.2@45.87,27.785 46.15,28.065 v1(46.5,28.065) R114.1@47.17,28.065
ETH1.TX_CTL: R164.1 U1.AD14 | length 1.2
  Top Layer w0.09: U1.AD14@62.875,36.325 63.146,36.325 63.221,36.25 v3(63.305,36.25)
  Bottom Layer w0.11: v3(63.305,36.25) 63.305,35.54 R164.1@63.319,35.525
ETH1.TXD0: R167.1 U1.AE13 | length 8.3
  Top Layer w0.09: U1.AE13@62.375,35.825 62.625,35.575 62.625,34.075
  Top Layer w0.11: R167.1@61.545,28.065 61.545,28.845 62.625,29.925 62.625,34.075
ETH1.TXD1: R173.1 U1.AG14 | length 8.5
  Top Layer w0.11: R173.1@61.56,27.24 62.115,27.24 62.747,27.872 62.747,28.913 62.875,29.041 62.875,34.075 U1.AG14@62.875,34.825
ETH1.TXD2: R178.1 U1.AF14 | length 10
  Top Layer w0.09: U1.AF14@62.875,35.325 62.898,35.302 62.898,35.156 63.125,34.929 63.125,34.164 63.085,34.124 63.085,34.075
  Top Layer w0.11: R178.1@61.56,26.465 62.145,26.465 62.957,27.277 62.957,28.826 63.085,28.954 63.085,34.075
ETH1.TXD3: R185.1 U1.AE14 | length 11.6
  Top Layer w0.09: U1.AE14@62.875,35.825 63.125,35.575 63.125,35.221 63.305,35.041 63.305,34.075
  Top Layer w0.11: R185.1@61.56,25.59 62.331,25.59 63.167,26.426 63.167,28.739 63.305,28.877 63.305,34.075
EXP_GPIO2: CN5.3 R246.1 U1.Y6 | length 68.4
  Top Layer w0.09: U1.Y6@58.875,38.325 58.928,37.865 v3(58.939,37.77)
  Signal Layer 3 w0.1: v3(58.939,37.77) 58.939,37.394 57.665,36.12 57.665,33.975 54.859,31.169 54.859,30.73 63.042,22.548 67.529,22.548 67.538,22.538 71.155,22.538 71.63,22.063 72.512,22.063 75.27,19.305 80.585,19.305 82.409,21.129 82.576,21.129 v1(83.17,21.723)
  Bottom Layer w0.1: v1(83.17,21.723) 83.17,20.994 83.406,20.758 R246.1@84.074,20.758 84.563,20.758 86.049,22.244 87.25,22.244 88.344,23.338 89.455,23.338 92.556,20.238 95.432,20.238 96,19.669 96,19.563 95.995,19.558 95.995,12.685 CN5.3@97.27,11.41
EXP_GPIO3: CN5.5 R245.1 U1.V3 | length 78.9
  Top Layer w0.09: 56.183,38.89 56.188,38.895 56.553,38.895 56.733,39.075 57.125,39.075 U1.V3@57.374,39.324
  Top Layer w0.1: R245.1@48.805,39.873 48.812,39.866 v2(49.358,39.866) 49.83,39.394 50.019,39.394 50.021,39.392 50.476,39.392 50.478,39.394 53.081,39.394 53.381,39.094 55.843,39.094 56.047,38.89 56.183,38.89
  Signal Layer 3 w0.1: v2(49.358,39.866) 47.467,39.866 46.842,39.241 46.842,38.694 48.694,36.842 48.982,36.842 49.7,36.125 49.7,35.73 51.105,34.325 51.825,34.325 52.081,34.069 52.081,30.428 56.393,26.116 56.393,23.276 64.57,15.1 70.687,15.1 71.517,15.93 74.628,15.93 76.679,13.879 84.642,13.879 85.826,15.063 96.157,15.063 CN5.5@97.27,13.95
EXP_GPIO4: CN5.7 TP11.1 U1.AE4 | length 54.9
  Top Layer w0.09: 57.525,34.075 57.525,34.441 57.585,34.501 57.585,35.152 57.625,35.192 57.625,35.467 57.848,35.69 57.848,35.798 U1.AE4@57.875,35.825
  Top Layer w0.1: v2(57.275,31.8) 57.525,32.05 57.525,34.075
  Signal Layer 3 w0.1: v2(57.275,31.8) 56.721,31.246 56.721,29.928 62.173,24.476 67.209,24.476 67.708,24.975 71.553,24.975 72.463,24.065 78.297,24.065 79.377,22.985 79.43,22.985 v1(79.78,22.635)
  Bottom Layer w0.1: v1(79.78,22.635) 81.517,22.635 81.907,23.025 TP11.1@86.412,23.025 87.674,23.025 88.187,23.538 89.538,23.538 92.639,20.438 95.514,20.438 96.2,19.752 96.2,19.48 96.195,19.475 96.195,17.565 CN5.7@97.27,16.49
EXP_GPIO5: CN5.29 U1.AG10 | length 58.6
  Top Layer w0.09: 60.679,34.372 60.875,34.568 U1.AG10@60.875,34.825
  Top Layer w0.1: 60.679,34.372 60.623,34.316 60.623,33.097 v2(60.956,32.765)
  Signal Layer 3 w0.1: v2(60.956,32.765) 60.956,32.708 61.51,32.154 61.51,30.947 61.225,30.662 61.225,27.708 61.758,27.175 66.164,27.175 66.915,26.424 70.054,26.424 71.336,27.706 88.913,27.706 91.693,30.486 91.693,30.941 92.385,31.633 92.385,31.834 92.83,32.279 92.83,41.98 93,42.15 v1(93,43.15)
  Signal Layer 4 w0.1: v1(93,43.15) 93.086,43.064 93.254,43.064 93.36,42.959 93.609,42.959 93.8,43.15 95.99,43.15 CN5.29@97.27,44.43
EXP_GPIO6: CN5.31 U1.AD16 | length 94.3
  Top Layer w0.1: U1.AD16@63.875,36.325 64.219,36.271 v3(64.323,36.254)
  Signal Layer 3 w0.1: v1(91.824,15.875) 91.824,18.264 93.855,20.295 95.572,20.295 96,20.723 96,21.037 95.995,21.042 95.995,23.118 96.15,23.273 96.15,24.7 96.852,25.403 97.935,25.403 98.545,26.013 98.545,45.695 CN5.31@97.27,46.97
  Bottom Layer w0.1: v3(64.323,36.254) 64.33,36.248 64.33,35.966 64.438,35.858 64.438,34.135 64.379,34.075 63.187,32.883 63.187,23.983 62.08,22.876 62.08,16.571 63.431,15.22 71.049,15.22 77.169,21.34 79.854,21.34 80.244,21.73 81.505,21.73 82.17,21.065 82.17,20.067 82.168,20.064 82.168,18.256 83.674,16.75 86.535,16.75 87.176,16.11 87.494,16.11 87.729,15.875 v1(91.824,15.875)
EXP_GPIO7: CN5.26 U1.R5 | length 73.8
  Top Layer w0.1: v3(58.325,40.376) U1.R5@58.375,40.825
  Signal Layer 2 w0.1: v1(89.5,25.126) 93.235,28.861 93.235,37.855 CN5.26@94.73,39.35
  Signal Layer 3 w0.1: v3(58.325,40.376) 58.315,40.366 57.72,40.366 56.885,39.531 56.885,34.338 54.059,31.512 54.059,30.304 57.826,26.537 57.826,25.467 61.965,21.327 65.437,21.327 67.785,18.979 74.465,18.979 74.939,18.505 80.917,18.505 82.74,20.329 84.118,20.329 85.304,21.514 85.77,21.514 86.471,22.215 86.471,24.107 86.808,24.444 88.818,24.444 v1(89.5,25.126)
EXP_GPIO8: CN5.24 U1.AF10 | length 48.4
  Top Layer w0.09: U1.AF10@60.875,35.325 61.125,35.075 61.125,34.485
  Top Layer w0.1: v2(60.973,33.601) 60.973,34.333 61.125,34.485
  Signal Layer 3 w0.1: v2(60.973,33.601) 61.71,32.865 61.71,30.864 61.425,30.579 61.425,27.791 61.841,27.375 66.247,27.375 66.997,26.624 69.971,26.624 71.289,27.942 88.866,27.942 91.493,30.569 91.493,31.024 92.185,31.716 92.185,31.917 92.63,32.362 92.63,32.943 v1(92.047,33.525)
  Signal Layer 4 w0.1: v1(92.047,33.525) 93.086,34.564 93.086,35.166 CN5.24@94.73,36.81
EXP_GPIO9: CN5.21 U1.AC9 | length 53.3
  Top Layer w0.09: 59.925,34.442 59.925,35.225 60.125,35.425 60.125,36.125 60.375,36.375 U1.AC9@60.375,36.825
  Top Layer w0.1: 59.925,34.442 60.023,34.344 60.023,32.093 60.451,31.666 60.469,31.666 v2(60.96,31.175)
  Signal Layer 3 w0.1: v2(60.96,31.175) 60.96,31.101 60.825,30.966 60.825,27.542 62.23,26.137 65.263,26.137 65.387,26.013 71.087,26.013 71.276,26.203 78.231,26.203 78.782,26.754 79.742,26.754 80.392,26.104 86.091,26.104 86.962,26.975 91.575,26.975 92.81,28.21 v1(92.81,31.658)
  Signal Layer 4 w0.1: v1(92.81,31.658) 92.826,31.674 92.826,32.083 93.778,33.035 96.035,33.035 CN5.21@97.27,34.27
EXP_GPIO10: CN5.19 U1.AF9 | length 49.8
  Top Layer w0.09: 60.125,34.59 60.125,35.075 U1.AF9@60.375,35.325
  Top Layer w0.1: 60.125,34.59 60.223,34.492 60.223,32.412 60.408,32.228 v2(60.408,32.204) ; 91.25,30.798 91.796,31.344 92.47,31.344 93.343,30.47 96.01,30.47 CN5.19@97.27,31.73 ; v1@91.251,29.025 91.251,30.798
  Signal Layer 3 w0.1: v2(60.408,32.204) 61.087,31.525 61.105,31.525 61.31,31.32 61.31,31.03 61.025,30.745 61.025,27.625 61.675,26.975 66.058,26.975 66.809,26.224 71.015,26.224 71.194,26.403 78.148,26.403 78.699,26.954 79.824,26.954 80.474,26.304 86.008,26.304 86.91,27.206 89.431,27.206 v1(91.25,29.025)
EXP_GPIO11: CN5.23 U1.AB8 | length 52.1
  Top Layer w0.1: v3(59.469,37.256) 59.802,37.313 U1.AB8@59.875,37.325
  Signal Layer 3 w0.1: v3(59.469,37.256) 59.469,36.102 61.497,34.075 61.91,33.662 61.91,30.782 61.625,30.496 61.625,27.874 61.924,27.575 66.329,27.575 67.08,26.824 69.889,26.824 71.206,28.142 88.783,28.142 91.293,30.651 91.293,31.107 91.985,31.799 91.985,32 92.047,32.062 v1(92.047,32.869)
  Signal Layer 4 w0.1: v1(92.047,32.869) 93.655,34.477 93.655,34.715 94.285,35.345 95.805,35.345 CN5.23@97.27,36.81
EXP_GPIO12: CN5.32 U1.AE17 | length 54.9
  Top Layer w0.09: U1.AE17@64.375,35.825 64.625,35.575 64.625,34.635
  Top Layer w0.1: 64.625,34.635 64.625,29.701 65.331,28.995 65.331,28.141 65.5,27.973 v1(65.5,26.55)
  Bottom Layer w0.1: v1(65.5,26.55) 66.235,27.285 67.799,27.285 69.98,29.466 86.704,29.466 86.719,29.48 87.071,29.48 87.085,29.466 90.016,29.466 93.425,32.874 93.425,45.028 93.855,45.457 93.855,46.095 CN5.32@94.73,46.97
